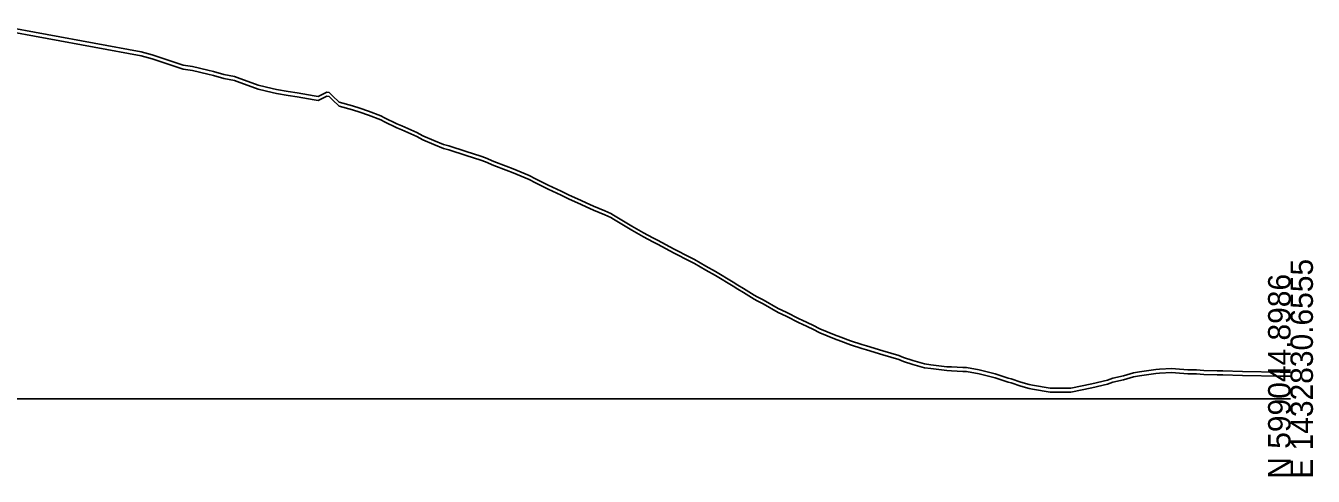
# Model space of a CAD drawing. Extents: x -26 to 2203, y -10 to 12201.
# Drawn here: x 442.1 to 602.8, y 10490.3 to 10546.6 of the extents above; entities that cross this region are included whole.
import ezdxf

# ---------------------------------------------------------------- set-up
doc = ezdxf.new("R2010")
doc.units = 0
for name, color, linetype in [('DESIGN - SHEET - Light Grid', 7, 'Continuous'), ('SURVEY - GROUND - Bottom of Topsoil Layer', 7, 'Continuous'), ('SURVEY - GROUND - Top of Ground', 7, 'Continuous')]:
    doc.layers.add(name, color=color, linetype=linetype)

msp = doc.modelspace()

# ---------------------------------------------------------------- linework, layer by layer
at = {"layer": 'DESIGN - SHEET - Light Grid'}
msp.add_line((300, 10500), (600, 10500), dxfattribs=at)
at = {"layer": 'SURVEY - GROUND - Bottom of Topsoil Layer'}
for p, q in [((438.83, 10546.13), (456.45, 10542.88)), ((456.45, 10542.88), (457.83, 10542.51)), ((457.83, 10542.51), (458.45, 10542.29)), ((458.45, 10542.29), (461.7, 10541.21)), ((461.7, 10541.21), (462.9, 10541.02)), ((462.9, 10541.02), (464.79, 10540.56)), ((464.79, 10540.56), (465.51, 10540.43)), ((465.51, 10540.43), (466.8, 10540.05)), ((466.8, 10540.05), (468.12, 10539.8)), ((468.12, 10539.8), (468.81, 10539.54)), ((468.81, 10539.54), (470.74, 10538.81)), ((470.74, 10538.81), (471.07, 10538.72)), ((471.07, 10538.72), (472.82, 10538.27)), ((472.82, 10538.27), (473.35, 10538.15)), ((473.35, 10538.15), (474.83, 10537.89)), ((474.83, 10537.89), (475.96, 10537.74)), ((475.96, 10537.74), (478.07, 10537.37)), ((478.57, 10537.29), (479.64, 10537.83)), ((479.64, 10537.83), (479.93, 10537.8)), ((479.93, 10537.8), (480.38, 10537.36)), ((478.07, 10537.37), (478.57, 10537.29)), ((480.38, 10537.36), (481.18, 10536.58)), ((481.18, 10536.58), (482.85, 10536.12)), ((482.85, 10536.12), (483.79, 10535.81)), ((483.79, 10535.81), (484.86, 10535.45)), ((484.86, 10535.45), (486.4, 10534.85)), ((486.4, 10534.85), (486.86, 10534.6)), ((486.86, 10534.6), (488.39, 10533.86)), ((488.39, 10533.86), (489.02, 10533.6)), ((489.02, 10533.6), (490.88, 10532.77)), ((490.88, 10532.77), (491.63, 10532.38)), ((491.63, 10532.38), (493.02, 10531.78)), ((493.02, 10531.78), (494.24, 10531.3)), ((494.24, 10531.3), (494.89, 10531.13)), ((494.89, 10531.13), (497.05, 10530.39)), ((497.05, 10530.39), (498.9, 10529.81)), ((498.9, 10529.81), (499.46, 10529.61)), ((499.46, 10529.61), (500.5, 10529.17)), ((500.5, 10529.17), (502.07, 10528.58)), ((502.07, 10528.58), (502.91, 10528.23)), ((502.91, 10528.23), (504.92, 10527.39)), ((504.92, 10527.39), (505.71, 10526.99)), ((505.71, 10526.99), (507.3, 10526.21)), ((507.3, 10526.21), (508.93, 10525.47)), ((508.93, 10525.47), (509.91, 10524.97)), ((509.91, 10524.97), (510.94, 10524.51)), ((510.94, 10524.51), (512.52, 10523.79)), ((512.52, 10523.79), (512.95, 10523.57)), ((512.95, 10523.57), (514.37, 10522.98)), ((514.37, 10522.98), (515.13, 10522.65)), ((515.13, 10522.65), (515.46, 10522.46)), ((515.46, 10522.46), (517.74, 10521.09)), ((517.74, 10521.09), (519.2, 10520.25)), ((519.2, 10520.25), (520.35, 10519.61)), ((520.35, 10519.61), (520.97, 10519.33)), ((520.97, 10519.33), (523.03, 10518.19)), ((523.03, 10518.19), (524.98, 10517.21)), ((524.98, 10517.21), (525.57, 10516.9)), ((525.57, 10516.9), (526.99, 10516.09)), ((526.99, 10516.09), (528.19, 10515.42)), ((528.19, 10515.42), (530.41, 10514.08)), ((530.41, 10514.08), (531, 10513.7)), ((531, 10513.7), (531.69, 10513.28)), ((531.69, 10513.28), (533.01, 10512.45)), ((533.01, 10512.45), (533.41, 10512.24)), ((533.41, 10512.24), (534.15, 10511.85)), ((534.15, 10511.85), (536.02, 10510.8)), ((536.02, 10510.8), (537.02, 10510.31)), ((537.02, 10510.31), (538.63, 10509.5)), ((538.63, 10509.5), (539.03, 10509.32)), ((539.03, 10509.32), (540.35, 10508.7)), ((540.35, 10508.7), (541.24, 10508.26)), ((541.24, 10508.26), (543.04, 10507.51)), ((543.04, 10507.51), (543.85, 10507.19)), ((543.85, 10507.19), (545.05, 10506.76)), ((545.05, 10506.76), (546.47, 10506.27)), ((546.47, 10506.27), (547.05, 10506.1)), ((547.05, 10506.1), (549.08, 10505.5)), ((549.08, 10505.5), (551.07, 10504.91)), ((551.07, 10504.91), (551.69, 10504.65)), ((551.69, 10504.65), (552.85, 10504.28)), ((552.85, 10504.28), (554.3, 10503.88)), ((554.3, 10503.88), (555.08, 10503.76)), ((555.08, 10503.76), (557.09, 10503.51)), ((557.09, 10503.51), (557.67, 10503.48)), ((557.67, 10503.48), (559.09, 10503.42)), ((559.09, 10503.42), (559.52, 10503.4)), ((559.52, 10503.4), (561.1, 10503.11)), ((561.1, 10503.11), (562.13, 10502.86)), ((562.13, 10502.86), (563.1, 10502.61)), ((563.1, 10502.61), (564.74, 10502.07)), ((577.8, 10502.08), (579.16, 10502.37)), ((579.16, 10502.37), (580.41, 10502.75)), ((580.41, 10502.75), (581.16, 10502.86)), ((581.16, 10502.86), (583.17, 10503.17)), ((583.17, 10503.17), (583.64, 10503.21)), ((583.64, 10503.21), (585.17, 10503.27)), ((585.17, 10503.27), (585.64, 10503.25)), ((585.64, 10503.25), (587.18, 10503.13)), ((587.18, 10503.13), (588.25, 10503.11)), ((588.25, 10503.11), (589.19, 10503.04)), ((589.19, 10503.04), (590.86, 10502.99)), ((590.86, 10502.99), (591.54, 10502.99)), ((591.54, 10502.99), (594.01, 10502.89)), ((594.01, 10502.89), (598.69, 10502.82)), ((598.69, 10502.82), (600, 10502.82)), ((564.74, 10502.07), (565.11, 10501.97)), ((565.11, 10501.97), (566.33, 10501.58)), ((566.33, 10501.58), (567.36, 10501.3)), ((567.36, 10501.3), (567.8, 10501.21)), ((567.8, 10501.21), (569.97, 10500.84)), ((569.97, 10500.84), (571.54, 10500.83)), ((571.54, 10500.83), (572.58, 10500.84)), ((572.58, 10500.84), (575.19, 10501.35)), ((575.19, 10501.35), (577.15, 10501.84)), ((577.15, 10501.84), (577.8, 10502.08))]:
    msp.add_line(p, q, dxfattribs=at)
at = {"layer": 'SURVEY - GROUND - Top of Ground'}
for p, q in [((438.83, 10546.63), (456.45, 10543.38)), ((456.45, 10543.38), (457.83, 10543.01)), ((457.83, 10543.01), (458.45, 10542.79)), ((458.45, 10542.79), (461.7, 10541.71)), ((461.7, 10541.71), (462.9, 10541.52)), ((462.9, 10541.52), (464.79, 10541.06)), ((464.79, 10541.06), (465.51, 10540.93)), ((465.51, 10540.93), (466.8, 10540.55)), ((466.8, 10540.55), (468.12, 10540.3)), ((468.12, 10540.3), (468.81, 10540.04)), ((468.81, 10540.04), (470.74, 10539.31)), ((470.74, 10539.31), (471.07, 10539.22)), ((471.07, 10539.22), (472.82, 10538.77)), ((472.82, 10538.77), (473.35, 10538.65)), ((473.35, 10538.65), (474.83, 10538.39)), ((474.83, 10538.39), (475.96, 10538.24)), ((475.96, 10538.24), (478.07, 10537.87)), ((478.07, 10537.87), (478.57, 10537.79)), ((478.57, 10537.79), (479.64, 10538.33)), ((479.64, 10538.33), (479.93, 10538.3)), ((479.93, 10538.3), (480.38, 10537.86)), ((480.38, 10537.86), (481.18, 10537.08)), ((481.18, 10537.08), (482.85, 10536.62)), ((482.85, 10536.62), (483.79, 10536.31)), ((483.79, 10536.31), (484.86, 10535.95)), ((484.86, 10535.95), (486.4, 10535.35)), ((486.4, 10535.35), (486.86, 10535.1)), ((486.86, 10535.1), (488.39, 10534.36)), ((488.39, 10534.36), (489.02, 10534.1)), ((489.02, 10534.1), (490.88, 10533.27)), ((490.88, 10533.27), (491.63, 10532.88)), ((491.63, 10532.88), (493.02, 10532.28)), ((493.02, 10532.28), (494.24, 10531.8)), ((494.24, 10531.8), (494.89, 10531.63)), ((494.89, 10531.63), (497.05, 10530.89)), ((497.05, 10530.89), (498.9, 10530.31)), ((498.9, 10530.31), (499.46, 10530.11)), ((499.46, 10530.11), (500.5, 10529.67)), ((500.5, 10529.67), (502.07, 10529.08)), ((502.07, 10529.08), (502.91, 10528.73)), ((502.91, 10528.73), (504.92, 10527.89)), ((504.92, 10527.89), (505.71, 10527.49)), ((505.71, 10527.49), (507.3, 10526.71)), ((507.3, 10526.71), (508.93, 10525.97)), ((508.93, 10525.97), (509.91, 10525.47)), ((509.91, 10525.47), (510.94, 10525.01)), ((510.94, 10525.01), (512.52, 10524.29)), ((512.52, 10524.29), (512.95, 10524.07)), ((512.95, 10524.07), (514.37, 10523.48)), ((514.37, 10523.48), (515.13, 10523.15)), ((515.13, 10523.15), (515.46, 10522.96)), ((515.46, 10522.96), (517.74, 10521.59)), ((517.74, 10521.59), (519.2, 10520.75)), ((519.2, 10520.75), (520.35, 10520.11)), ((520.35, 10520.11), (520.97, 10519.83)), ((520.97, 10519.83), (523.03, 10518.69)), ((523.03, 10518.69), (524.98, 10517.71)), ((524.98, 10517.71), (525.57, 10517.4)), ((525.57, 10517.4), (526.99, 10516.59)), ((526.99, 10516.59), (528.19, 10515.92)), ((528.19, 10515.92), (530.41, 10514.58)), ((530.41, 10514.58), (531, 10514.2)), ((531, 10514.2), (531.69, 10513.78)), ((531.69, 10513.78), (533.01, 10512.95)), ((533.01, 10512.95), (533.41, 10512.74)), ((533.41, 10512.74), (534.15, 10512.35)), ((534.15, 10512.35), (536.02, 10511.3)), ((536.02, 10511.3), (537.02, 10510.81)), ((537.02, 10510.81), (538.63, 10510)), ((538.63, 10510), (539.03, 10509.82)), ((539.03, 10509.82), (540.35, 10509.2)), ((540.35, 10509.2), (541.24, 10508.76)), ((541.24, 10508.76), (543.04, 10508.01)), ((543.04, 10508.01), (543.85, 10507.69)), ((543.85, 10507.69), (545.05, 10507.26)), ((545.05, 10507.26), (546.47, 10506.77)), ((546.47, 10506.77), (547.05, 10506.6)), ((547.05, 10506.6), (549.08, 10506)), ((549.08, 10506), (551.07, 10505.41)), ((551.07, 10505.41), (551.69, 10505.15)), ((551.69, 10505.15), (552.85, 10504.78)), ((552.85, 10504.78), (554.3, 10504.38)), ((554.3, 10504.38), (555.08, 10504.26)), ((555.08, 10504.26), (557.09, 10504.01)), ((557.09, 10504.01), (557.67, 10503.98)), ((557.67, 10503.98), (559.09, 10503.92)), ((559.09, 10503.92), (559.52, 10503.9)), ((559.52, 10503.9), (561.1, 10503.61)), ((561.1, 10503.61), (562.13, 10503.36)), ((562.13, 10503.36), (563.1, 10503.11)), ((563.1, 10503.11), (564.74, 10502.57)), ((564.74, 10502.57), (565.11, 10502.47)), ((565.11, 10502.47), (566.33, 10502.08)), ((575.19, 10501.85), (577.15, 10502.34)), ((577.15, 10502.34), (577.8, 10502.58)), ((577.8, 10502.58), (579.16, 10502.87)), ((579.16, 10502.87), (580.41, 10503.25)), ((580.41, 10503.25), (581.16, 10503.36)), ((581.16, 10503.36), (583.17, 10503.67)), ((583.17, 10503.67), (583.64, 10503.71)), ((583.64, 10503.71), (585.17, 10503.77)), ((585.17, 10503.77), (585.64, 10503.75)), ((585.64, 10503.75), (587.18, 10503.63)), ((587.18, 10503.63), (588.25, 10503.61)), ((588.25, 10503.61), (589.19, 10503.54)), ((589.19, 10503.54), (590.86, 10503.49)), ((590.86, 10503.49), (591.54, 10503.49)), ((591.54, 10503.49), (594.01, 10503.39)), ((594.01, 10503.39), (598.69, 10503.32)), ((598.69, 10503.32), (600, 10503.32)), ((566.33, 10502.08), (567.36, 10501.8)), ((567.36, 10501.8), (567.8, 10501.71)), ((567.8, 10501.71), (569.97, 10501.34)), ((569.97, 10501.34), (571.54, 10501.33)), ((571.54, 10501.33), (572.58, 10501.34)), ((572.58, 10501.34), (575.19, 10501.85))]:
    msp.add_line(p, q, dxfattribs=at)

# ---------------------------------------------------------------- texts
at = {"layer": 'DESIGN - SHEET - Light Grid'}
for s, p in [('E 1432830.6555', (602.8, 10490)), ('N 599044.8986', (600, 10490))]:
    msp.add_text(s, height=2.8, rotation=90, dxfattribs=at).set_placement(p)

doc.saveas('drawing.dxf')
